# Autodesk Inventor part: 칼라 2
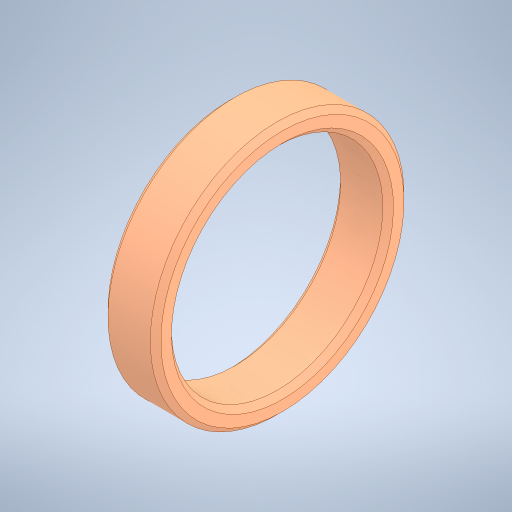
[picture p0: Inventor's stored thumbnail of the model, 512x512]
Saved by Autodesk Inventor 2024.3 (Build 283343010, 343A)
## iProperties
Created: 2025-11
Part Number: 칼라 2
Material: 강철, 연강
Document SubType Name: Modeling
Designer: PC2-15
Density: 7.85 g/cm^3
Appearance: 기본값
Author: jhkim
Sending System: Autodesk Inventor 2026
Preprocessor: ST-DEVELOPER v20.1
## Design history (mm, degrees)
node "칼라 21"
node "솔리드2"
node "솔리드1"
